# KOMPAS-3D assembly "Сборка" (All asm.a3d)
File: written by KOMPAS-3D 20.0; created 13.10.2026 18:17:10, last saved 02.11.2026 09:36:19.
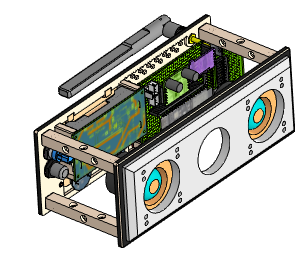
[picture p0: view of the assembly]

Document properties: Полное имя файла: D:\myProjects\Progect_esp32\box_compas\All asm.a3d

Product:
- Part/product: Сборка
    Масса: 3.1999
  - Component [assembly]: Сборка  | Масса: 1.58002; source file: сборки компонентов\Back_Panel_Сборка_v3.a3d
  - Component [assembly]: Сборка  | Масса: 1.6131; source file: корпус\корпус v1 asm.a3d
  - Component [detail]: Деталь  | Масса: 0.00678464; source file: переключатели и кнопки\Индикатор емкости литиевой батареи GBL 18650.m3d

Referenced files in D:\myProjects\Progect_esp32\box_compas\корпус\: корпус v1 asm.a3d
Referenced files in D:\myProjects\Progect_esp32\box_compas\сборки компонентов\: Back_Panel_Сборка_v3.a3d
Referenced files in D:\myProjects\Progect_esp32\box_compas\переключатели и кнопки\: Индикатор емкости литиевой батареи GBL 18650.m3d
